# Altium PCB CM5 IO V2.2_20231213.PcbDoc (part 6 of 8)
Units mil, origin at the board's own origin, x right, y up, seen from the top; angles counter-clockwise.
Board outline 6299.61 x 3544.09 mil, 4 copper layers (Top, GND, Power, Bottom), stack 35.4 mil thick; 482 components, 404 nets, 1857 pads, 2731 vias.
Unrouted connection lines stored in the file: 1872.
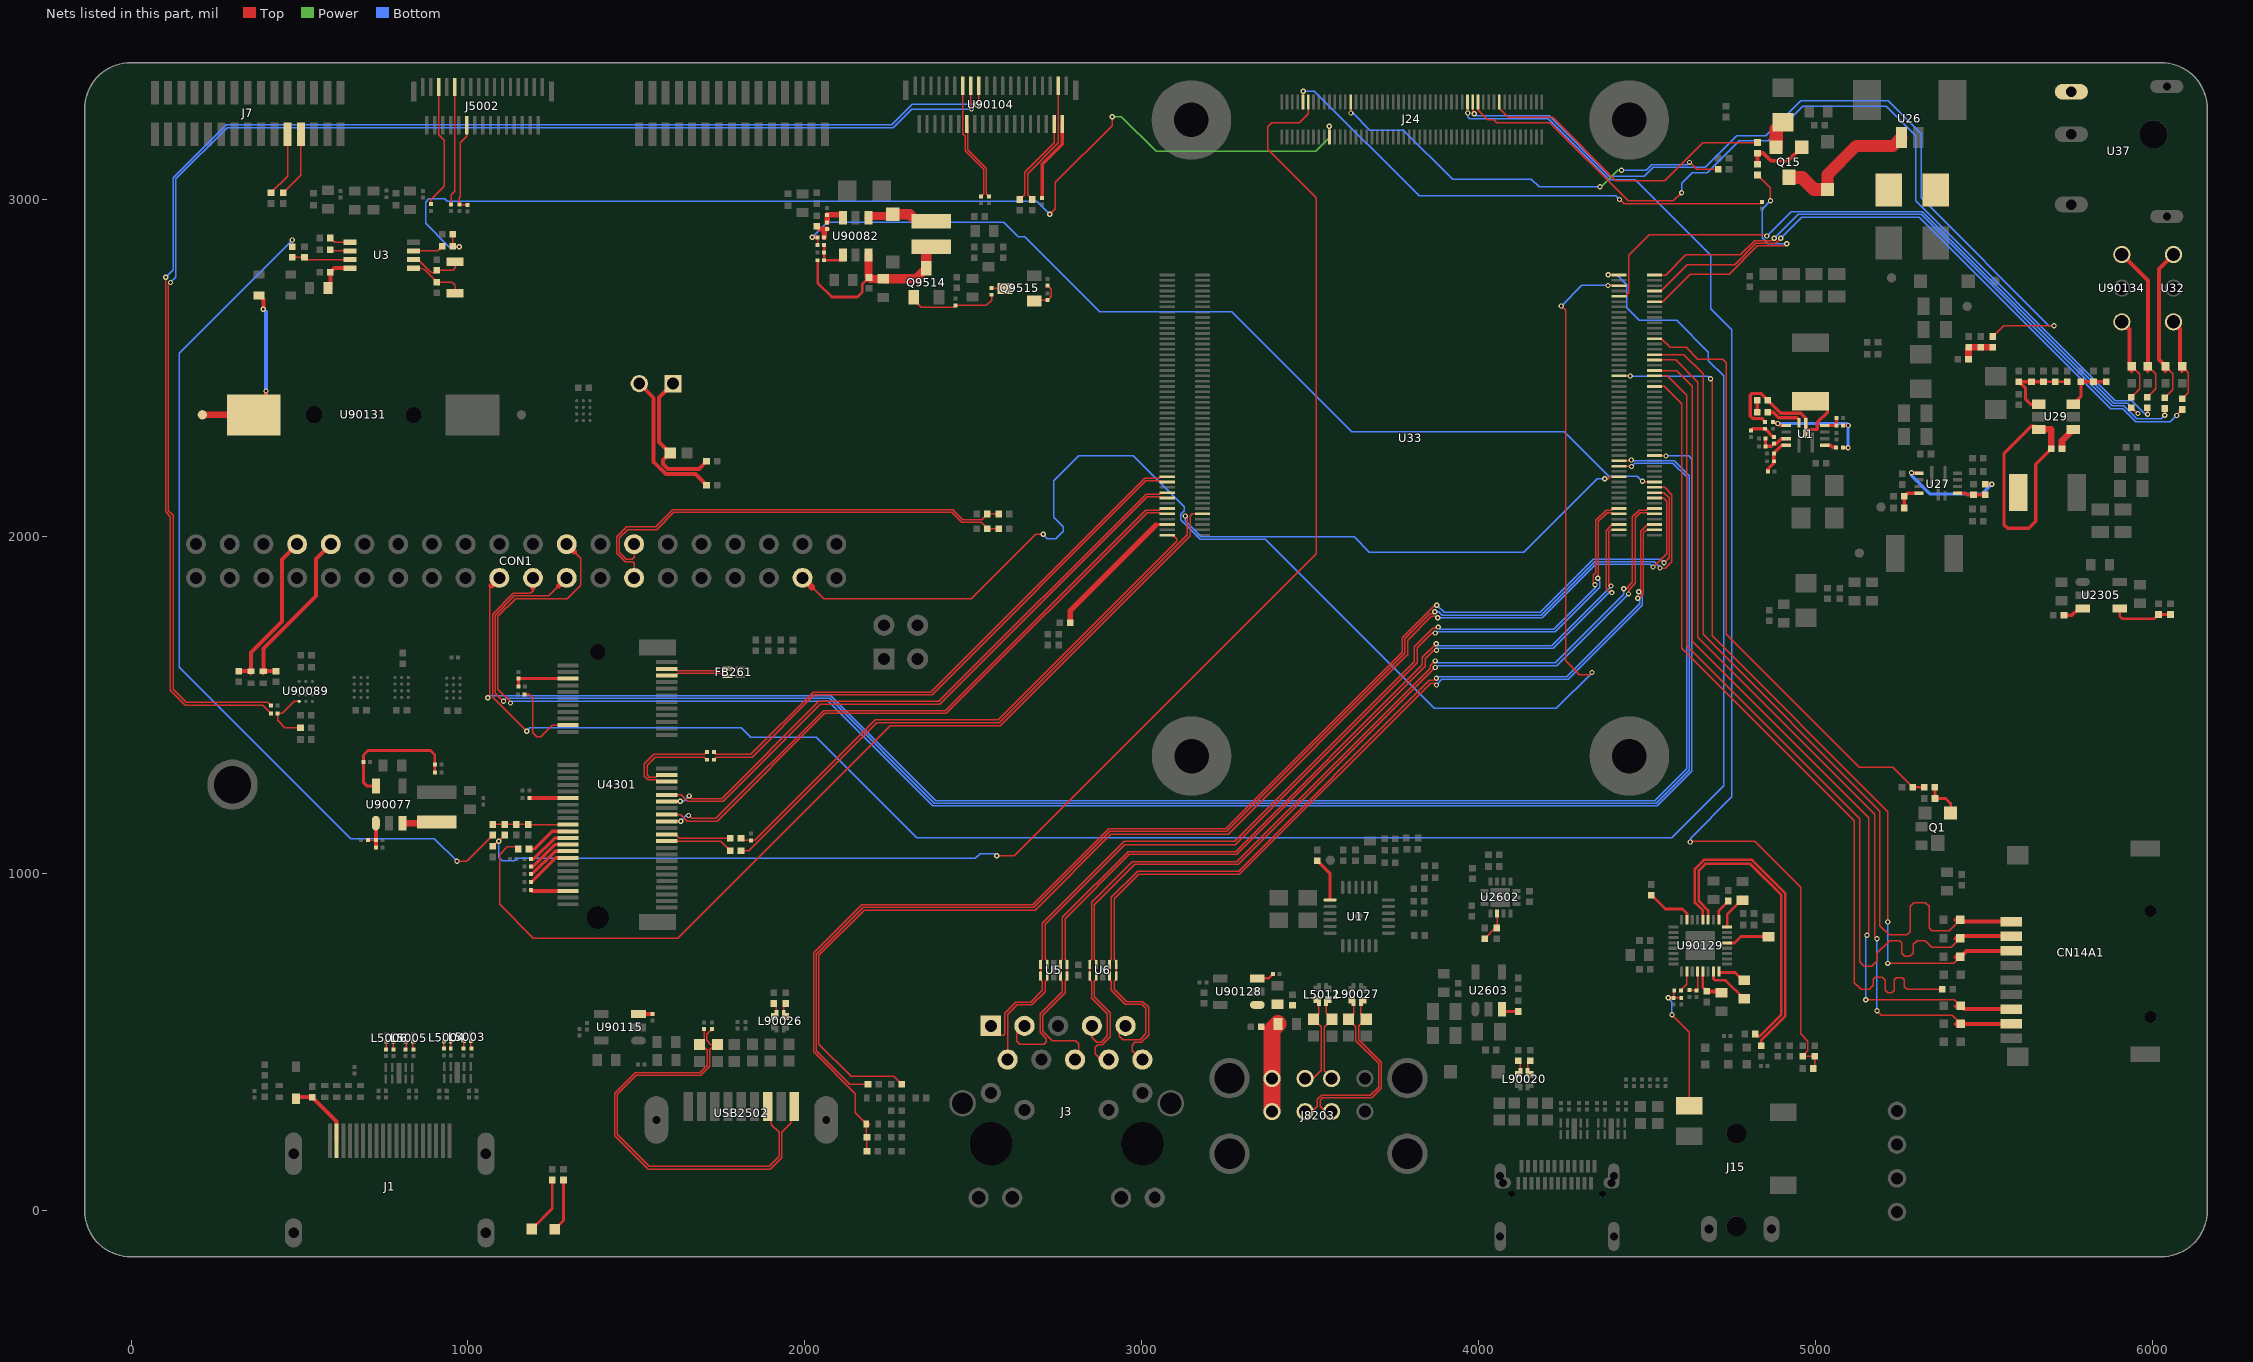
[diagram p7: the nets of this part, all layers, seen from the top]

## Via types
v1: diameter 15.75, hole 7.87, Top to Bottom, 2292 vias
v2: diameter 19.68, hole 11.81, Top to Bottom, 439 vias

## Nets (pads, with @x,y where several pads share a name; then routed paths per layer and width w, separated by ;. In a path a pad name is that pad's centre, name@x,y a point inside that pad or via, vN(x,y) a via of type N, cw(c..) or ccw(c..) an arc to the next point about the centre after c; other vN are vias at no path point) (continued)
N42932: C141.1 R151.1 R153.2 R154.2 | length 107.7
  Top w19.68: R151.1@5452.76,2524.61 5452.76,2560.04 C141.1@5453.74,2561.02 R154.2@5489.17,2561.02 R153.2@5524.61,2561.02
N43092: C143.1 R155.2 U27.6 | length 82.8
  Top w9.84: R155.2@5261.81,2083.66 C143.1@5261.81,2118.11
  Top w9.96: C143.1@5261.81,2118.11 5271.65,2127.95 U27.6@5306.1,2127.95
N43384: R156.1 U27.3 | length 322
  Top w9.84: v1(5283.46,2187.99) 5286.82,2187.01 U27.3@5306.1,2187.01 ; R156.1@5502.95,2154.53 v1(5521.65,2154.53)
  Bottom w9.84: v1(5283.46,2187.99) 5283.46,2181.06 5339.53,2125 5492.13,2125 v1(5521.65,2154.53)
N43388: C144.1 R156.2 U27.9 | length 84.7
  Top w9.84: U27.9@5420.28,2127.95 5443.9,2127.95 5448.82,2123.03 C144.1@5467.52,2123.03 R156.2@5502.95,2123.03
N43540: D45.1 D46.1 U37.1
N43676: C145.2 L13.1 U29.6 | length 788.7
  Top w9.84: U29.6@5661.42,2316.93 5651.57,2326.77 5639.57,2326.77 5558.07,2245.28 5558.07,2034.45 5568.9,2023.62 5631.89,2023.62 5652.56,2044.29 5652.56,2213.58 C145.2@5698.82,2259.84
  Top w19.68: U29.6@5661.42,2316.93 5698.82,2316.93 C145.2@5698.82,2259.84
N43804: C145.1 U29.1 | length 70.9
  Top w19.68: C145.1@5730.31,2259.84 5730.31,2283.46 U29.1@5763.78,2316.93
N46864: CON1.8 D49.2 R167.1 | length 470
  Top w11.81: R167.1@319.88,1599.41 D49.2@356.3,1599.41 356.3,1655.51 447.83,1747.05 447.83,1931.26 CON1.8@492.94,1976.36
N46956: CON1.10 D48.2 R168.1 | length 497.3
  Top w11.81: R168.1@430.12,1599.41 D48.2@392.72,1599.41 392.72,1666.34 549.21,1822.83 549.21,1932.63 CON1.10@592.94,1976.36
N87861: C1.1 D1.2 J1.18 | length 211.3
  Top w11.81: D1.2@490.16,330.71 490.16,335.63 C1.1@537.4,335.63 610.24,262.79 J1.18@610.24,206.69
N113472: C90425.1 L5003.4 R952.2 | length 23.5
  Top w3.94: L5003.4@1007.87,501.97 1007.87,481.3 C90425.1@1009.84,479.33
N113574: C90426.1 L5003.3 R953.2 | length 26.4
  Top w3.94: C90426.1@987.2,479.33 R953.2@987.2,502.95 988.98,502.95 L5003.3@988.98,501.97
N113748: C90427.1 L5004.4 R954.2 | length 24
  Top w3.94: L5004.4@947.83,500.98 R954.2@948.82,501.97 C90427.1@948.82,479.33
N113850: C90420.1 L5004.3 R955.2 | length 23.9
  Top w3.94: C90420.1@928.15,479.33 R955.2@928.15,501.97 928.94,501.18 L5004.3@928.94,500.98
N114042: C90421.1 L5005.4 R956.2 | length 23.5
  Top w3.94: L5005.4@835.63,500 835.63,479.33 C90421.1@837.6,477.36
N114144: C90422.1 L5005.3 R957.2 | length 23.4
  Top w3.94: C90422.1@814.96,477.36 816.73,479.13 L5005.3@816.73,500
N114322: C90424.1 L5006.4 R958.2 | length 23
  Top w3.94: L5006.4@777.56,500 777.56,478.35 C90424.1@778.54,477.36
N114424: C90423.1 L5006.3 R959.2 | length 24
  Top w3.94: C90423.1@756.89,477.36 757.87,478.35 R959.2@757.87,500.98
N131672: C90399.1 R95155.2 R95159.1 R95581.2 U4301.50 | length 222.9
  Top w3.94: R95155.2@1073.78,1144.67 R95581.2@1109.21,1144.67 R95159.1@1143.66,1144.67 C90399.1@1179.09,1144.67 1179.71,1144.05 U4301.50@1296.47,1144.05
N131914: R95147.2 U4301.54 | length 135.3
  Top w9.84: R95147.2@1186.97,1042.31 1195.85,1042.31 1258.23,1104.68 U4301.54@1296.47,1104.68
N131962: R95148.2 U4301.56 | length 137.8
  Top w9.84: R95148.2@1186.97,1019.67 1186.97,1018.82 1191.85,1018.82 1258.03,1085 U4301.56@1296.47,1085
N132002: R95149.2 U4301.58 | length 139
  Top w9.84: R95149.2@1186.97,997.03 1186.97,996.18 1189.1,996.18 1258.23,1065.31 U4301.58@1296.47,1065.31
N132062: R95150.2 U4301.60 | length 140.2
  Top w9.84: R95150.2@1186.97,974.4 1186.97,973.55 1187.82,973.55 1259.9,1045.63 U4301.60@1296.47,1045.63
N132134: R95152.2 U4301.70 | length 111
  Top w11.81: R95152.2@1186.97,950.77 1190.54,947.2 U4301.70@1296.47,947.2
N132294: L5011.1 U90077.3 | length 105.8
  Top w19.68: U90077.3@805.08,1148.61 L5011.1@907.48,1148.61
  Top w27.56: L5011.1@907.48,1148.61 L5011.1@907.48,1152
N132462: C269.1 R95209.2 R95239.2 U90077.1 | length 96.5
  Top w3.94: R95239.2@702.76,1098.43 C269.1@726.38,1098.43 C269.1@726.34,1098.46
  Top w11.81: C269.1@726.34,1098.46 U90077.1@726.34,1148.61 ; R95209.2@726.38,1075.79 C269.1@726.38,1098.43
N132478: C266.2 R95210.1 R95281.2 U90077.5 | length 398
  Top w7.87: R95210.1@689.92,1329.71 689.92,1350.35 703.74,1364.17 888.78,1364.17 901.57,1351.38 R95281.2@901.57,1321.85 C266.2@901.57,1298.23
  Top w9.84: R95210.1@689.92,1329.71 689.92,1268.7 699.78,1258.85 U90077.5@726.34,1258.85
N135689: FB261.3 R95141.1 U4301.3 | length 194.4
  Top w3.94: U4301.3@1589.78,1606.65 1616.14,1606.65 1621.42,1601.38 1752.95,1601.38 1758.86,1607.28 FB261.3@1764.76,1607.28 1764.76,1607.78 R95141.1@1779.04,1607.78
N135722: FB261.4 R95142.1 U4301.5 | length 195.7
  Top w3.94: U4301.5@1589.78,1586.97 1617.13,1586.97 1623.66,1593.5 1751.97,1593.5 1759.84,1585.63 FB261.4@1764.76,1585.63 1779.04,1585.63 R95142.1@1779.04,1585.14
N135883: C90392.2 U4301.35 | length 283.5
  Top w3.94: U4301.35@1589.78,1291.69 1563.35,1291.69 1557.09,1285.43 1538.39,1285.43 1531.5,1292.32 1531.5,1320.87 1555.12,1344.49 1701.77,1344.49 C90392.2@1709.65,1336.61
N135887: C90393.2 U4301.37 | length 310.1
  Top w3.94: U4301.37@1589.78,1272.01 1563.62,1272.01 1558.07,1277.56 1534.45,1277.56 1523.62,1288.39 1523.62,1324.8 1551.18,1352.36 1701.77,1352.36 C90393.2@1709.65,1360.24
N136147: R95144.2 U4301.53 | length 193.4
  Top w3.94: U4301.53@1589.78,1114.53 1616.14,1114.53 1627.32,1103.35 R95144.2@1778.54,1103.35
N136159: R95146.2 U4301.55 | length 200.3
  Top w3.94: U4301.55@1589.78,1094.84 1750.63,1094.84 R95146.2@1778.54,1066.93
N138588: R95143.2 U4301.42 | length 114.7
  Top w11.81: R95143.2@1182.05,1223.41 1182.49,1222.79 U4301.42@1296.47,1222.79
N139019: R95145.2 U4301.52 | length 137.2
  Top w9.84: R95145.2@1181.06,1071.84 1197.47,1071.84 1250,1124.37 U4301.52@1296.47,1124.37
N146153: R95467.2 U90104.2 | length 244.4
  Top w9.84: R95467.2@2703.74,3003.94 2703.74,3103.35 2763.78,3163.39 U90104.2@2763.78,3223.43
N146193: R95468.2 U90104.4 | length 266.8
  Top w3.94: R95468.2@2637.8,2999.02 2652.56,3013.78 2652.56,3079.72 2740.16,3167.32 U90104.4@2740.16,3223.43
N146409: R95469.2 U90104.23 | length 4397.4
  Top w3.94: v1(103.35,2768.7) 103.35,2071.85 117.13,2058.07 117.13,1542.32 160.43,1499.02 390.75,1499.02 R95469.2@415.35,1474.41 ; v1(2509.84,3280.51) 2515.75,3286.42 U90104.23@2515.75,3336.61
  Bottom w3.94: v1(103.35,2768.7) 125,2790.35 125,3063.3 282.17,3220.47 2257.87,3220.47 2318.9,3281.5 2505.91,3281.5 2508.37,3279.04 v1(2509.84,3280.51)
N146477: R95470.2 U90104.25 | length 4356.2
  Top w3.94: v1(117.13,2752.95) 111.22,2747.05 111.22,2075.79 125,2062.01 125,1546.26 164.37,1506.89 405.51,1506.89 R95470.2@415.35,1497.05 ; U90104.25@2492.13,3336.61 2492.13,3269.68 v1(2494.09,3267.72)
  Bottom w3.94: v1(117.13,2752.95) 132.87,2768.7 132.87,3060.04 285.43,3212.6 2261.81,3212.6 2316.93,3267.72 v1(2494.09,3267.72)
N146511: R95471.2 U90104.26 | length 242.9
  Top w3.94: U90104.26@2480.31,3223.43 2483.27,3220.48 2483.27,3146.65 2538.39,3091.54 2538.39,3015.75 R95471.2@2546.26,3007.87
N146519: R95472.2 U90104.27 | length 357.7
  Top w3.94: U90104.27@2468.5,3336.61 2468.5,3193.9 2475.39,3187.01 2475.39,3143.39 2530.51,3088.27 2530.51,3015.75 R95472.2@2522.63,3007.87
N16719677: C750.2 J5002.20 R715.2 | length 268.2
  Top w3.94: J5002.20@996.06,3219.5 996.06,3187.01 977.36,3168.31 977.36,3006.89 974.41,3003.94 C750.2@974.41,2984.25 997.05,2984.25 R715.2@998.03,2983.27
N16719795: J5002.23 R814.2 | length 352.9
  Top w3.94: R814.2@949.8,2984.25 949.8,3012.8 960.63,3023.62 J5002.23@960.63,3332.68
N16719909: J5002.27 R95580.2 | length 370.3
  Top w3.94: R95580.2@889.76,2985.24 889.76,2999.02 929.14,3038.39 929.14,3175.2 913.38,3190.95 J5002.27@913.38,3332.68
N16722445: C90408.1 C90410.1 L5000.1 Q9514.3 R95039.1 U90082.6 | length 606.3
  Top w7.87: R95039.1@2037.4,2818.9 2037.4,2751.97 2079.72,2709.65 2155.51,2709.65 2170.28,2724.41 2170.28,2748.03 C90410.1@2189.96,2767.72
  Top w23.62: U90082.6@2187.99,2834.65 2187.99,2769.68 C90410.1@2189.96,2767.72 2193.89,2763.78 C90408.1@2232.28,2763.78
  Top w27.56: C90408.1@2232.28,2763.78 2328.74,2763.78 Q9514.3@2360.24,2795.28
  Top w31.5: Q9514.3@2360.24,2795.28 2360.24,2859.25 L5000.1@2375,2859.25
N16722481: D5000.1 L5000.2 U90082.1 | length 206.8
  Top w23.62: U90082.1@2187.99,2944.88 2187.99,2950.3 2260.82,2950.3 D5000.1@2260.82,2955.71
  Top w31.5: D5000.1@2260.82,2955.71 2311.02,2955.71 2332.68,2934.06 L5000.2@2375,2934.06
N16722531: Q9514.1 R95041.2 R95044.1 | length 271.5
  Top w3.94: Q9514.1@2322.84,2708.66 2322.84,2701.77 2344.49,2680.12 2441.93,2680.12 R95041.2@2446.85,2685.04 2538.39,2685.04 2554.13,2700.79 R95044.1@2554.13,2716.54
N16722773: R95039.2 R95137.2 R95578.2 U90082.4 | length 117.1
  Top w7.87: R95137.2@2057.08,2864.17 R95578.2@2057.08,2841.54 R95039.2@2057.08,2818.9 2113.19,2818.9 U90082.4@2113.19,2834.65
N16722853: Q9515.3 R95044.2 | length 39.8
  Top w3.94: R95044.2@2554.13,2736.22 2592.52,2736.22 Q9515.3@2593.5,2735.24
N16722887: R95071.1 R95072.2 U90082.3 | length 78.7
  Top w15.75: R95072.2@2065.94,2931.1 R95071.1@2065.94,2953.74 2113.19,2953.74 U90082.3@2113.19,2944.88
N16723025: Q9515.1 R95042.2 R95043.1 | length 94
  Top w3.94: Q9515.1@2680.12,2697.84 2687.01,2697.84 2689.96,2700.79 R95043.1@2719.49,2700.79 2719.97,2700.79 2731.3,2712.12 2731.3,2732.28 R95042.2@2719.49,2744.09
N16723155: C90448.1 R95072.1 R95073.2 | length 58.4
  Top w15.75: C90448.1@2035.43,2919.29 2043.3,2911.42 2057.08,2911.42 ; R95073.2@2057.08,2886.81 2057.08,2911.42 ; R95072.1@2065.94,2911.42 2057.08,2911.42
N16734367: R95115.1 U1.8 | length 110.8
  Top w9.84: R95115.1@4857.28,2368.11 4873.03,2368.11 4889.76,2351.38 4943.89,2351.38 4949.8,2345.47 U1.8@4949.8,2336.61
N16734375: C90489.1 R95115.2 | length 35.4
  Top w9.84: R95115.2@4825.79,2368.11 C90489.1@4825.79,2403.54
N16734501: C90489.2 L5002.1 R95121.1 U1.7 | length 542.9
  Top w9.84: R95121.1@4849.41,2338.58 4849.41,2338.83 4838.83,2349.41 4812.28,2349.41 4805.12,2356.57 4805.12,2418.31 4810.04,2423.23 4838.51,2423.23 4857.74,2404 4857.28,2404 C90489.2@4857.28,2403.54 4895.67,2365.16 4954.72,2365.16 4969.49,2350.39 U1.7@4969.49,2320.86 4969.49,2304.85 4981.57,2316.93 5003.94,2316.93 5003.94,2337.6 5034.45,2368.11 5034.45,2400.59 L5002.1@4984.25,2400.59
N16734773: C90487.1 R95114.2 R95122.1 U1.12 | length 108.7
  Top w9.84: R95122.1@4857.28,2191.93 4857.28,2198.82 4875,2216.54 C90487.1@4875,2222.44 R95114.2@4875,2246.06 4898.62,2269.68 U1.12@4912.4,2269.68
N16734781: C90481.1 R95118.1 R95121.2 | length 82.3
  Top w9.84: C90481.1@4807.09,2313.98 4812.01,2318.9 R95121.2@4849.41,2318.9 4848.95,2318.9 4848.95,2318.44 4873.1,2294.29 R95118.1@4875.98,2294.29
N16735007: R95116.1 R95118.2 R95120.2 U1.11 | length 94
  Top w9.84: R95120.2@4850.39,2289.37 R95116.1@4850.39,2266.73 4868.11,2266.73 R95118.2@4875.98,2274.61 4882.35,2274.61 4897.11,2289.37 U1.11@4912.4,2289.37
N16735153: C90482.1 R95113.1 R95119.1 U1.9 | length 352.9
  Top w9.84: C90482.1@4873.03,2338.58 4873.03,2337.83 v1(4886.81,2334.65) 4892.71,2328.74 U1.9@4912.4,2328.74 ; R95113.1@5079.72,2262.8 v1(5095.47,2262.8) ; R95119.1@5080.71,2328.74 v1(5096.46,2328.74)
  Bottom w9.84: v1(4886.81,2334.65) 5090.55,2334.65 v1(5096.46,2328.74) 5095.47,2327.76 v1(5095.47,2262.8)
N16735287: R95113.2 U1.3 | length 36.9
  Top w9.84: U1.3@5026.58,2269.68 5043.31,2269.68 5049.21,2263.78 5060.04,2263.78 R95113.2@5060.04,2262.8
N16735291: R95117.1 R95119.2 U1.6 | length 57.1
  Top w9.84: U1.6@5026.58,2328.74 5035.44,2328.74 R95119.2@5061.02,2328.74 R95117.1@5061.02,2351.38
N16750686: L90020.1 R91188.2 R95546.1 | length 46.8
  Top w3.94: R95546.1@4151.57,403.54 4151.08,403.54 4151.08,403.05 4144.69,409.45 L90020.1@4144.69,412.4 4144.69,435.04 R91188.2@4152.56,442.91
N16750718: L90020.2 R91189.2 R95547.1 | length 44.9
  Top w3.94: R95547.1@4117.13,403.54 4117.37,403.54 4117.37,403.3 4123.03,408.96 L90020.2@4123.03,412.4 4123.03,437.01 R91189.2@4117.13,442.91
N16754417: R91193.1 U90115.3 | length 42.5
  Top w11.81: U90115.3@1505.91,581.69 1505.91,582.38 R91193.1@1547.7,582.38
N16755970: L90026.1 R95550.1 R95551.2 | length 43.9
  Top w3.94: R95550.1@1942.91,574.8 1942.67,574.8 1942.67,574.56 1937.01,580.22 L90026.1@1937.01,583.66 1937.01,607.28 R95551.2@1942.91,613.19
N16756054: L90026.2 R95552.2 R95553.1 | length 45.8
  Top w3.94: R95552.2@1907.48,613.19 1915.35,605.31 L90026.2@1915.35,583.66 1915.35,580.71 1908.96,574.31 1908.96,574.8 R95553.1@1908.46,574.8
N16763522: C90774.1 C90775.1 C90776.1 C90777.1 J8203.1 J8203.5 U90128.1 | length 267.8
  Top w51.18: J8203.1@3385.85,292.5 J8203.5@3385.85,390.93 3385.85,535.01 C90775.1@3403.77,552.93
N16763712: R95556.1 U90128.3 | length 51.6
  Top w7.87: U90128.3@3342.52,687.99 3375.98,687.99 R95556.1@3388.78,700.79
N16763936: ED21.1 J8203.2 L90027.3 R249.1 | length 565.4
  Top w3.94: J8203.2@3484.28,292.5 3504.12,292.5 3520.67,309.06 3520.67,328.89 3533.31,341.54 3678.15,341.54 3702.11,365.5 3702.11,435.38 3635.1,502.38 3635.1,544.03 ED21.1@3612.55,566.59 3628.29,582.34 L90027.3@3628.29,616.39 3628.29,618.85 3623.13,624.02 3623.13,623.28 R249.1@3622.39,623.28
N16763952: ED22.1 J8203.6 L5012.1 R253.2 | length 286.7
  Top w3.94: J8203.6@3484.28,390.93 3507.87,390.93 3531.72,414.77 3531.72,543.97 ED22.1@3509.16,566.52 3524.91,582.27 L5012.1@3524.91,616.33 3524.91,619.77 3519.25,625.43 3519.25,625.18 R253.2@3519,625.18
N16764114: ED20.1 J8203.3 L90027.4 R250.1 | length 570.4
  Top w3.94: J8203.3@3563.02,292.5 3544.29,292.5 3528.54,308.25 3528.54,325.63 3536.57,333.66 3681.41,333.66 3709.98,362.23 3709.98,438.64 3643.14,505.48 3643.14,547.24 3665.7,569.8 ED20.1@3665.7,566.59 3649.95,582.34 L90027.4@3649.95,616.39 3649.95,618.85 3655.11,624.02 3655.11,623.28 R250.1@3655.85,623.28
N16764134: ED6.1 J8203.7 L5012.2 R254.2 | length 263.7
  Top w3.94: R254.2@3552.47,625.18 3552.22,625.18 3552.22,625.43 3546.56,619.77 L5012.2@3546.56,616.33 3546.56,583.75 ED6.1@3563.98,566.34 3540.35,542.72 3540.35,413.59 J8203.7@3563.02,390.93
N16766215: R396.2 U90129.31 | length 146.4
  Top w7.87: R396.2@4511.81,935.04 4553.15,893.7 4603.53,893.7 4617.31,879.92 U90129.31@4617.31,861.84
N16766259: C560.1 U90129.28 | length 963.2
  Top w7.87: U90129.28@4664.55,861.84 4664.55,888.78 4640.75,912.59 4640.75,1012.8 4667.32,1039.37 4810.04,1039.37 4909.45,939.96 4909.45,575.79 4837.6,503.94 C560.1@4837.6,488.19
N16766319: C561.1 U90129.27 | length 910.1
  Top w7.87: U90129.27@4680.3,861.84 4680.3,889.81 4652.56,917.55 4652.56,1007.9 4672.22,1027.56 4805.12,1027.56 4897.64,935.04 4897.64,580.71 4833.66,516.73 4825.79,516.73 C561.1@4819.88,522.64
N16766443: C563.1 U90129.25 | length 67.2
  Top w7.87: U90129.25@4711.8,861.84 4711.8,888.96 C563.1@4740.16,917.32
N16766591: C564.1 U90129.24 | length 101.2
  Top w7.87: U90129.24@4736.4,840.18 4736.4,877.59 4778.73,919.91 C564.1@4782.66,919.91
N16766729: C565.1 U90129.21 | length 131.7
  Top w9.06: U90129.21@4736.4,792.94 4758.49,792.94 4777.56,812.01 4859.25,812.01 C565.1@4859.25,811.02
N16767009: R90340.1 U90129.10 | length 63.5
  Top w3.94: R90340.1@4599.32,652.28 4617.31,670.28 U90129.10@4617.31,708.29
N16767013: R95558.2 R95573.1 U90129.12 | length 78.5
  Top w3.94: R95558.2@4624.38,652.74 4645.67,652.74 R95573.1@4645.67,652.56 4648.81,655.7 U90129.12@4648.81,708.29
N16767017: C569.1 C570.1 U90129.13 | length 111.2
  Top w7.87: U90129.13@4664.55,708.29 4664.55,661.05 C570.1@4676.36,649.24
  Top w11.81: C570.1@4676.36,649.24 4719.67,649.24 C569.1@4719.67,645.3
N16767025: C568.1 U90129.15 | length 137.7
  Top w7.87: U90129.15@4696.05,708.29 4696.05,686.64 4700.6,682.09 4732.28,682.09 C568.1@4787.4,626.97
N16767069: C568.2 U90129.16 | length 88.2
  Top w7.87: U90129.16@4711.8,708.29 4711.8,705.34 4760.21,705.34 4783.46,682.09 C568.2@4787.4,682.09
N16767177: J15.4 R90337.2 R90340.2 R90341.1 | length 406.9
  Top w3.94: v1(4562.01,629.92) R90341.1@4577.76,629.92 ; v1(4572.83,579.72) 4624.04,528.52 J15.4@4624.04,310.22 ; R90340.2@4579.63,652.28 4577.76,650.41 R90341.1@4577.76,629.92 ; R90337.2@4600.39,629.92 R90341.1@4577.76,629.92
  Bottom w3.94: v1(4562.01,629.92) 4572.83,619.09 v1(4572.83,579.72)
N16770554: C90615.1 U3.1 Y2.2 | length 166.1
  Top w3.94: U3.1@838.57,2795.39 856.3,2795.39 cw(c856.3,2770.26) 874.06,2788.03 907.48,2754.61 C90615.1@907.48,2753.94 947.83,2753.94 cw(c947.83,2740.16) 961.61,2740.16 Y2.2@961.61,2721.46
N16770682: C90616.1 U3.2 Y2.1 | length 166.9
  Top w3.94: U3.2@838.57,2820.98 852.25,2820.98 886.86,2786.37 ccw(c898.62,2798.13) 898.62,2781.5 907.48,2781.5 C90616.1@907.48,2789.37 951.77,2789.37 ccw(c951.77,2799.21) 961.61,2799.21 Y2.1@961.61,2813.98
N16770702: C90617.1 R95373.2 U3.8 | length 117.1
  Top w11.81: R95373.2@584.65,2736.22 591.54,2736.22 C90617.1@591.54,2783.46 603.46,2795.39 U3.8@649.59,2795.39
N16770836: R95028.1 R95374.1 U3.7 | length 174.1
  Top w3.94: R95028.1@478.35,2827.76 R95374.1@514.76,2827.76 521.54,2820.98 U3.7@649.59,2820.98
N16770894: R121.2 U3.3 | length 90.3
  Top w3.94: U3.3@838.57,2846.57 909.56,2846.57 R121.2@923.23,2860.24
N16770902: R120.1 U3.6 | length 61.9
  Top w3.94: R120.1@591.54,2850.39 591.54,2846.57 U3.6@649.59,2846.57
N16771020: R95377.1 U3.5 | length 63.3
  Top w3.94: R95377.1@591.54,2884.84 604.22,2872.16 U3.5@649.59,2872.16
N16772975: D2.1 TP16.1 U90131.1 | length 552.2
  Top w11.81: U90131.1@364.25,2360.24 400.59,2360.24 v1(400.59,2431.1) ; D2.1@379.92,2714.92 392.72,2702.12 v1(392.72,2673.23)
  Top w19.68: TP16.1@211.61,2360.24 U90131.1@364.25,2360.24
  Bottom w11.81: v1(392.72,2673.23) 400.59,2665.35 v1(400.59,2431.1)
N16776017: ED4806.1 R95495.2 U32.1 | length 470.6
  Top w3.94: R95495.2@6035.43,2410.43 6059.06,2434.06 6059.06,2482.68 ED4806.1@6037.4,2504.33
  Top w11.81: ED4806.1@6037.4,2504.33 6017.72,2524.02 6017.72,2792.87 U32.1@6061.05,2836.2
N16801679: J7.4 R95570.2 | length 195.8
  Top w3.94: R95570.2@451.77,3018.7 503.94,3070.87 J7.4@503.94,3192.91
N16801700: J7.5 R95571.2 | length 194.6
  Top w3.94: R95571.2@415.35,3018.7 464.57,3067.91 J7.5@464.57,3192.91
N16808352: C153.1 R158.2 R159.2 R160.1 R95572.2 U29.4 | length 249.5
  Top w7.87: R95572.2@5675.2,2458.66 R158.2@5710.63,2458.66 R159.2@5746.06,2458.66
  Top w9.84: U29.4@5661.42,2391.73 5636.81,2391.73 5622.05,2406.5 5622.05,2438.98 C153.1@5602.36,2458.66 R160.1@5639.76,2458.66 R95572.2@5675.2,2458.66
N16810900: C148.2 R157.2 R161.1 U29.3 | length 151.1
  Top w9.84: U29.3@5763.78,2391.73 5786.42,2414.37 R161.1@5786.42,2458.66 C148.2@5823.82,2458.66 R157.2@5861.22,2458.66
N16815803: R2612.1 U2603.3 | length 52.1
  Top w7.87: U2603.3@4067.91,596.45 4074.8,589.57 R2612.1@4117.13,589.57
N16815967: R2613.2 R95599.2 U2602.5 | length 91.8
  Top w3.94: R2613.2@4017.35,805.87 4048.85,837.37 R95599.2@4052.78,837.37 4053.77,838.35 U2602.5@4053.77,880.28
N16884567: J24.92 R9241.2 | length 1535.3
  Top w3.94: J24.92@3477.76,3288.58 3478.35,3288.58 v1(3478.35,3320.87) ; v1(4417.32,2999.02) 4419.29,2999.02 4431.1,2987.2 4835.63,2987.2 R9241.2@4840.55,2992.13
  Bottom w3.94: v1(3478.35,3320.87) 3511.81,3320.87 3822.83,3009.84 4406.5,3009.84 v1(4417.32,2999.02)
N16901877: ED9203.1 R95582.2 U32.3 | length 254.8
  Top w3.94: R95582.2@6086.61,2407.48 6105.31,2426.18 6105.31,2485.63 ED9203.1@6086.61,2504.33
  Top w11.81: U32.3@6061.05,2636.2 6080.36,2616.89 6080.36,2510.93 6086.61,2504.68 ED9203.1@6086.61,2504.33
N16901998: R95583.2 R95598.1 U4301.6 | length 171.1
  Top w9.84: R95583.2@1149.61,1554.13 R95598.1@1149.61,1577.76 1296.47,1577.76 U4301.6@1296.47,1577.13
N16914632: ED9204.1 R95584.2 U90134.3 | length 255.8
  Top w3.94: R95584.2@5936.02,2412.4 5960.63,2437.01 5960.63,2480.71 ED9204.1@5937.01,2504.33
  Top w11.81: U90134.3@5907.9,2636.2 5930.76,2613.35 5930.76,2510.93 5937.01,2504.68 ED9204.1@5937.01,2504.33
N16914672: ED9205.1 R95585.2 U90134.1 | length 475.4
  Top w3.94: R95585.2@5983.27,2412.4 6007.87,2437.01 6007.87,2481.69 ED9205.1@5985.24,2504.33
  Top w11.81: U90134.1@5907.9,2836.2 5985.24,2758.87 ED9205.1@5985.24,2504.33
N16916775: R95586.2 U4301.20 | length 255.2
  Top w3.94: R95586.2@1168.27,1530.5 1181.1,1530.5 1191.93,1519.67 1191.93,1416.54 1203.94,1404.53 1215.55,1404.53 1250.35,1439.33 U4301.20@1296.47,1439.33
N16941764: LED4.2 R95602.1 | length 156.4
  Top w7.87: LED4.2@1257.62,-56.16 1283.46,-30.31 R95602.1@1283.46,89.57
N16946224: ED7104.1 J10.1 R7120.2 | length 421.9
  Top w11.81: J10.1@1608.27,2452.76 1566.93,2411.42 1566.93,2280.12 ED7104.1@1600,2247.05 1579.17,2226.22 1579.17,2214.13 1593.5,2199.8 1685.04,2199.8 R7120.2@1707.68,2222.44
N16946250: J10.2 R7125.1 | length 435.5
  Top w11.81: J10.2@1508.27,2452.76 1551.18,2409.84 1551.18,2219.85 1586.98,2184.06 1675.2,2184.06 R7125.1@1707.68,2151.57
N17002627: CON1.27 R95609.2 R95610.2 | length 1342.2
  Top w3.94: CON1.27@1492.94,1876.36 1492.94,1919.66 1488.39,1924.21 1466.73,1924.21 1441.34,1949.61 1441.34,1998.68 1471.01,2028.35 1556.91,2028.35 1607.3,2078.74 2438.58,2078.74 2468.11,2049.21 2524.61,2049.21 R95609.2@2541.34,2065.94 R95610.2@2574.8,2065.94
N17002814: CON1.28 R95611.1 R95612.1 | length 1312.6
  Top w3.94: CON1.28@1492.94,1976.36 1492.94,1937.82 1487.2,1932.09 1469.99,1932.09 1449.21,1952.87 1449.21,1995.42 1473.48,2019.68 1560.04,2019.68 1611.22,2070.87 2435.32,2070.87 2464.85,2041.34 2522.64,2041.34 R95612.1@2541.34,2022.64 R95611.1@2574.8,2022.64
N17057562: Q1.1 R12.2 R13.1 | length 114.7
  Top w7.87: R13.1@5352.85,1255.41 5353.35,1255.41 R12.2@5353.35,1221.46 5384.84,1221.46 5399.63,1206.67 Q1.1@5399.63,1178.86
N17076875: R2311.2 R95606.2 U2305.4 | length 181.8
  Top w7.87: U2305.4@5901.58,1785.43 5901.58,1762.8 5909.45,1754.92 6003.94,1754.92 R95606.2@6016.73,1767.72 R2311.2@6052.17,1767.72
N17076883: R2322.1 U2305.3 | length 63.3
  Top w9.84: R2322.1@5736.22,1765.75 5759.84,1765.75 5779.53,1785.43 U2305.3@5791.34,1785.43
N17101033: D37.1 Q15.3 U26.1 | length 439.7
  Top w35.43: D37.1@5034.45,3028.54 5034.45,3072.83 5120.08,3158.46 5229.33,3158.46 U26.1@5253.94,3183.07
  Top w39.37: Q15.3@4919.93,3065.25 4919.93,3064.32 4959.3,3064.32 4995.08,3028.54 D37.1@5034.45,3028.54
N17101108: Q15.1 R214.1 R215.1 | length 190.6
  Top w11.81: R214.1@4826.77,3103.35 R215.1@4826.77,3136.81 4843.5,3136.81 4866.14,3114.17 4917.8,3114.17 Q15.1@4957.93,3154.31
N17101132: Q15.2 R353.1 | length 82.6
  Top w39.37: Q15.2@4881.93,3154.31 4881.93,3207.72 R353.1@4902.56,3228.35
N17122158: R95616.1 U33.106 | length 429.9
  Top w7.87: 3041.34,2033.46 3042.92,2034.84 U33.106@3075.2,2034.84
  Top w15.75: R95616.1@2787.4,1743.11 2787.4,1779.53 3041.34,2033.46
N169418181: LED4.1 R95603.2 | length 170.8
  Top w7.87: LED4.1@1189.23,-56.05 1250,4.72 R95603.2@1250,89.57
OVCJ: R96.2 U17.1 | length 132.8
  Top w9.84: R96.2@3519.69,1037.4 3558.26,998.83 U17.1@3558.26,920.57
PCIE20_0_REFCLKN: U33.112 U4301.49 | length 1877.6
  Top w3.94: U4301.49@1589.78,1153.9 1589.78,1154.53 v1(1630.91,1154.53) ; v1(1654.53,1171.26) 1663.39,1162.4 1735.24,1162.4 2055.12,1482.28 2415.94,1482.28 3011.42,2077.76 3050.2,2077.76 3054.53,2082.09 U33.112@3075.2,2082.09
  Bottom w3.94: v1(1630.91,1154.53) 1647.64,1171.26 v1(1654.53,1171.26)
PCIE20_0_REFCLKP: U33.110 U4301.47 | length 1873.9
  Top w3.94: U4301.47@1589.78,1173.58 1631.89,1173.58 1650.94,1154.53 1739.17,1154.53 2059.06,1474.41 2419.88,1474.41 3015.35,2069.88 3051.18,2069.88 3054.72,2066.34 U33.110@3075.2,2066.34
PCIE20_0_RXN: U33.118 U4301.43 | length 1871.9
  Top w3.94: U4301.43@1589.78,1212.95 1589.78,1213.58 v1(1629.92,1213.58) ; v1(1656.5,1229.33) 1664.37,1221.46 1752.95,1221.46 2041.34,1509.84 2396.94,1509.84 3012.09,2125 3051.18,2125 3055.51,2129.33 U33.118@3075.2,2129.33
  Bottom w3.94: v1(1629.92,1213.58) 1640.75,1213.58 v1(1656.5,1229.33)
PCIE20_0_RXP: U33.116 U4301.41 | length 1869
  Top w3.94: U4301.41@1589.78,1232.64 1632.87,1232.64 1651.93,1213.58 1756.89,1213.58 2045.28,1501.97 2400.2,1501.97 3015.35,2117.13 3052.17,2117.13 3055.71,2113.58 U33.116@3075.2,2113.58
PCIE20_0_TXN: C90393.1 U33.124 | length 1690.5
  Top w3.94: C90393.1@1729.33,1360.24 1737.2,1352.36 1839.57,1352.36 2024.61,1537.4 2373.03,1537.4 3007.87,2172.24 3050.2,2172.24 3054.53,2176.57 U33.124@3075.2,2176.57
PCIE20_0_TXP: C90392.1 U33.122 | length 1690.2
  Top w3.94: C90392.1@1729.33,1336.61 1737.2,1344.49 1842.83,1344.49 2027.87,1529.53 2376.97,1529.53 3011.81,2164.37 3052.17,2164.37 3055.71,2160.83 U33.122@3075.2,2160.83
PCIE20X1_2_CLKREQN_M0: R95144.1 R95151.1 U33.102 | length 1703
  Top w3.94: R95144.1@1810.04,1103.35 1815.94,1097.44 R95151.1@1839.57,1097.44 1851.38,1097.44 2208.66,1454.72 2572.83,1454.72 3103.35,1985.24 3103.35,1991.81 3091.81,2003.35 U33.102@3075.2,2003.35
PCIE20X1_2_PERSTN_M0: R95145.1 U33.109 | length 2899.8
  Top w3.94: R95145.1@1149.57,1071.84 1142.66,1078.74 1117.13,1078.74 1093.5,1055.12 1093.5,907.48 1193.9,807.09 1622.05,807.09 2252.95,1437.99 2579.72,1437.99 3142.72,2000.98 3142.72,2060.04 3149.02,2066.34 U33.109@3179.13,2066.34
PCIE20X1_2_WAKEN_M0: R95146.1 U33.24 | length 3201.7
  Top w3.94: R95146.1@1810.04,1066.93 1832.68,1066.93 2212.6,1446.85 2576.1,1446.85 3133.86,2004.61 3133.86,2055.12 v1(3128.94,2060.04) ; v1(4373.03,2170.28) 4383.46,2170.28 4389.76,2176.57 U33.24@4415.75,2176.57
  Bottom w3.94: v1(3128.94,2060.04) 3128.94,2046.26 3176.59,1998.6 3629.35,1998.6 3675.2,1952.76 4132.87,1952.76 4350.39,2170.28 v1(4373.03,2170.28)
PHY1_LED0_Y1: R6.1 U33.19 | length 3813.5
  Top w3.94: R6.1@2187.01,374.02 2132.87,374.02 2033.46,473.43 2033.46,759.84 2172.24,898.62 2679.43,898.62 2904.83,1124.02 3252.14,1124.02 3780.2,1652.08 3780.2,1695.1 3854.78,1769.68 3863.19,1769.68 v1(3869.09,1775.59) ; U33.19@4520.47,2145.08 4550.79,2145.08 4572.44,2123.43 4572.44,2113.19 4572.44,1924.8 4553.15,1905.51 v1(4537.4,1905.51)
  Bottom w3.94: v1(3869.09,1775.59) 3880.91,1775.59 3890.75,1765.75 4184.73,1765.75 4343.2,1924.21 4520.47,1924.21 4538.39,1906.3 4538.39,1905.51 v1(4537.4,1905.51)
PHY1_LED1_G: D3.2 R2.2 R3.1 U33.17 | length 3959.1
  Top w3.94: R2.2@2184.06,175.2 R3.1@2184.06,216.54 2182.09,218.5 D3.2@2182.09,255.91 2149.61,288.39 2149.61,346.15 2025.59,470.16 2025.59,763.78 2168.31,906.5 2676.12,906.5 2901.52,1131.89 3248.87,1131.89 3772.32,1655.34 3772.32,1698.36 3869.23,1795.28 v1(3875,1795.28) ; U33.17@4520.47,2129.33 4548.82,2129.33 4564.57,2113.58 4564.57,1936.61 v1(4549.21,1921.26)
  Bottom w3.94: v1(3875,1795.28) 3896.65,1773.62 4181.47,1773.62 4339.93,1932.09 4537.4,1932.09 4548.72,1920.77 v1(4549.21,1921.26)
PHY1_LED2_Y: R5.1 U33.15 | length 3797.9
  Top w3.94: R5.1@2287.4,374.02 2263.78,397.64 2136.81,397.64 2041.34,493.11 2041.34,755.91 2176.18,890.75 2682.7,890.75 2908.1,1116.14 3255.4,1116.14 3784.79,1645.54 3788.07,1648.81 3788.07,1691.84 3858.04,1761.81 3874.02,1761.81 v1(3877.95,1757.87) ; v1(4516.73,1908.46) 4556.69,1948.43 4556.69,2103.35 4546.46,2113.58 U33.15@4520.47,2113.58
  Bottom w3.94: v1(3877.95,1757.87) 4187.99,1757.87 4346.46,1916.34 4508.86,1916.34 v1(4516.73,1908.46)
PHY1_MDI0+: J3.1 U5.1 U5.10 U33.12 | length 2837.5
  Top w3.94: J3.1@2551.39,547.01 2579.7,518.7 2589.57,518.7 2593.52,522.65 2593.52,584.65 2626,617.13 2669.29,617.13 2704.72,652.56 2704.72,679.13 2699.03,684.83 U5.1@2699.03,695.14 U5.10@2699.03,729.58 2699.03,739.17 2704.72,744.87 2704.72,852.15 2947.06,1094.49 3275.26,1094.49 3808.57,1627.8 3808.57,1671.68 3863.27,1726.38 3878.94,1726.38 v1(3878.94,1730.31) ; v1(4344.49,1856.3) 4341.54,1856.3 4338.58,1859.25 4338.58,1883.86 4346.46,1891.73 4346.46,2047.08 4377.14,2077.76 4392.72,2077.76 4397.05,2082.09 U33.12@4415.75,2082.09
  Bottom w3.94: v1(3878.94,1730.31) 3884.84,1724.41 4222.44,1724.41 4344.49,1846.46 v1(4344.49,1856.3)
PHY1_MDI0-: J3.2 U5.2 U5.9 U33.10 | length 2838.2
  Top w3.94: J3.2@2601.39,447.01 2601.39,580.71 2629.93,609.25 2673.23,609.25 2712.6,648.62 2712.6,678.15 2718.72,684.27 U5.2@2718.72,695.14 U5.9@2718.72,729.58 2718.72,740.16 2712.6,746.28 2712.6,848.43 2948.82,1084.65 3276.56,1084.65 3816.45,1624.54 3816.45,1668.4 3860.65,1712.6 v1(3870.08,1712.6) ; v1(4352.36,1875) 4354.33,1875 4354.33,2043.81 4380.4,2069.88 4392.72,2069.88 4396.26,2066.34 U33.10@4415.75,2066.34
  Bottom w3.94: v1(3870.08,1712.6) 3874.02,1716.54 4226.38,1716.54 4358.27,1848.43 4358.27,1866.14 4350.89,1873.52 v1(4352.36,1875)
PHY1_MDI1+: J3.3 U5.4 U5.7 U33.4 | length 2821.2
  Top w3.94: J3.3@2651.39,547.01 2633.86,547.01 2628.94,542.09 2628.94,501.97 2637.8,493.11 2709.65,493.11 2716.54,500 2716.54,508.86 2697.83,527.56 2697.83,582.68 2763.78,648.62 2763.78,678.15 2758.08,683.85 U5.4@2758.08,695.14 U5.7@2758.08,729.58 2758.08,739.17 2763.78,744.87 2763.78,868.89 2958.87,1063.98 3278.16,1063.98 3832.2,1618.01 3832.2,1640.27 v1(3873.03,1681.1) ; v1(4391.73,1852.36) 4389.76,1850.39 4385.83,1854.33 4385.83,2012.8 4392.13,2019.09 U33.4@4415.75,2019.09
  Bottom w3.94: v1(3873.03,1681.1) 3878.94,1675.2 4216.54,1675.2 4391.73,1850.39 v1(4391.73,1852.36)
PHY1_MDI1-: J3.6 U5.5 U5.6 U33.6 | length 2815.8
  Top w3.94: J3.6@2801.39,447.01 2812.99,458.61 2812.99,494.09 2804.13,502.95 2734.25,502.95 2705.71,531.5 2705.71,578.53 2771.65,644.48 2771.65,678.92 2777.77,685.04 U5.5@2777.77,695.14 U5.6@2777.77,729.58 2777.77,739.17 2771.65,745.29 2771.65,864.95 2962.81,1056.1 3281.42,1056.1 3840.07,1614.75 3840.07,1636.29 3865.2,1661.42 v1(3874.02,1661.42) ; v1(4393.7,1832.68) 4389.76,1832.68 4377.95,1844.49 4377.95,2009.84 4377.95,2016.73 4396.06,2034.84 U33.6@4415.75,2034.84
  Bottom w3.94: v1(3874.02,1661.42) 3879.92,1667.32 4220.47,1667.32 4387.8,1834.65 4391.73,1834.65 v1(4393.7,1832.68)
PHY1_MDI2+: J3.7 U6.1 U6.10 U33.11 | length 2803.8
  Top w3.94: J3.7@2851.39,547.01 2851.39,512.78 2865.16,499.02 2878.63,499.02 2897.64,518.03 2897.64,582.37 2850.39,629.61 2850.39,678.36 2844.7,684.06 U6.1@2844.7,695.14 U6.10@2844.7,729.58 2844.7,739.17 2850.39,744.87 2850.39,913.18 2971.67,1034.45 3282.04,1034.45 3855.82,1608.23 3855.82,1615.66 v1(3870.08,1629.92) ; v1(4430.12,1844.49) 4433.56,1841.04 4455.71,1863.19 4455.71,2058.07 4475.39,2077.76 4496.06,2077.76 4500.39,2082.09 U33.11@4520.47,2082.09
  Bottom w3.94: v1(3870.08,1629.92) 3875.98,1624.02 4226.38,1624.02 4430.12,1827.76 v1(4430.12,1844.49)
PHY1_MDI2-: J3.8 U6.2 U6.9 U33.9 | length 2806.4
  Top w3.94: J3.8@2901.39,447.01 2877.8,447.01 2861.22,463.58 2861.22,483.27 2869.09,491.14 2881.89,491.14 2905.51,514.76 2905.51,585.63 2858.27,632.87 2858.27,678.92 2864.39,685.04 U6.2@2864.39,695.14 U6.9@2864.39,729.58 2864.39,739.17 2858.27,745.29 2858.27,906.28 2978.56,1026.57 3285.3,1026.57 3868.96,1610.24 v1(3870.08,1610.24) ; v1(4443.9,1828.74) 4443.9,1840.24 4463.58,1859.93 4463.58,2054.13 4479.33,2069.88 4497.05,2069.88 4500.59,2066.34 U33.9@4520.47,2066.34
  Bottom w3.94: v1(3870.08,1610.24) 3875.98,1616.14 4231.3,1616.14 v1(4443.9,1828.74)
PHY1_MDI3+: J3.9 U6.4 U6.7 U33.3 | length 2804.1
  Top w3.94: J3.9@2951.39,547.01 2938.74,547.01 2933.07,541.34 2933.07,515.75 2942.91,505.91 2994.77,505.91 3011.81,522.95 3011.81,599.1 2999.69,611.22 2950.79,611.22 2909.45,652.56 2909.45,678.35 2903.75,684.06 U6.4@2903.75,695.14 U6.7@2903.75,729.58 2903.75,739.17 2909.45,744.87 2909.45,927.94 2987.41,1005.91 3286.91,1005.91 3853.21,1572.2 3867.55,1572.2 v1(3873.82,1578.47) ; v1(4471.46,1815.94) 4475.39,1815.94 4488.19,1828.74 4488.19,2009.84 4497.44,2019.09 U33.3@4520.47,2019.09
  Bottom w3.94: v1(3873.82,1578.47) 3878.03,1582.68 4260.83,1582.68 4477.36,1799.21 4477.36,1810.04 v1(4471.46,1815.94)
PHY1_MDI3-: J3.10 U6.5 U6.6 U33.5 | length 2809.8
  Top w3.94: J3.10@3001.39,447.01 2996.89,447.01 2970.47,473.43 2970.47,489.17 2979.33,498.03 2998.03,498.03 3019.69,519.68 3019.69,602.36 3002.95,619.09 2954.72,619.09 2918.31,655.51 2918.31,679.91 2923.44,685.04 U6.5@2923.44,695.14 U6.6@2923.44,729.58 2923.44,739.17 2917.32,745.29 2917.32,924 2990.37,997.05 3289.23,997.05 3856.45,1564.27 3868.11,1564.27 v1(3873.98,1558.41) ; v1(4474.41,1835.63) 4475.89,1834.15 4480.31,1838.58 4480.31,2014.02 4501.14,2034.84 U33.5@4520.47,2034.84
  Bottom w3.94: v1(3873.98,1558.41) 3890.37,1574.8 4264.76,1574.8 4485.24,1795.28 4485.24,1824.8 v1(4474.41,1835.63)
PWM4_M0: R214.2 U33.89 | length 756.8
  Top w3.94: U33.89@4520.47,2696.26 4545.67,2696.26 4626.97,2777.56 4742.13,2777.56 4825.79,2861.22 4906.5,2861.22 v1(4913.39,2868.11) ; R214.2@4826.77,3071.85 4865.16,3033.46 v1(4865.16,2995.08)
  Bottom w3.94: v1(4865.16,2995.08) 4840.55,2970.47 4840.55,2885.04 4857.48,2868.11 v1(4913.39,2868.11)
PWM11_M3: J24.18 R215.2 | length 921
  Top w3.94: J24.18@4060.43,3288.58 4060.43,3270.08 4065.94,3264.57 4065.94,3264.09 4086.92,3243.11 4218.5,3243.11 4406.5,3055.12 4551.18,3055.12 4664.37,3168.31 R215.2@4826.77,3168.31
PWM15_M1: R95073.1 R95137.1 U33.21 | length 2876.1
  Top w3.94: R95137.1@2037.4,2864.17 R95073.1@2037.4,2886.81 ; v1(4485.24,2163.39) 4485.24,2162.11 4520.47,2162.11 U33.21@4520.47,2160.83
  Top w9.84: v1(2021.65,2886.81) R95073.1@2037.4,2886.81
  Bottom w3.94: v1(2021.65,2886.81) 2065.94,2931.1 2590.24,2931.1 2632.76,2888.58 2652.76,2888.58 2875,2666.34 3266.17,2666.34 3622.47,2310.04 4252.95,2310.04 4384.84,2178.15 4470.47,2178.15 v1(4485.24,2163.39)
PWRON_L: R95495.1 U33.99 | length 1864.7
  Top w3.94: U33.99@4520.47,2775 4554.13,2775 4613.78,2834.65 4775.59,2834.65 4817.91,2876.97 4869.09,2876.97 v1(4875.98,2883.86) ; v1(6035.43,2359.25) R95495.1@6035.43,2378.94
  Bottom w3.94: v1(4875.98,2883.86) 4946.85,2954.72 5312.01,2954.72 5879.92,2386.81 5913.39,2386.81 5951.77,2348.43 6024.61,2348.43 v1(6035.43,2359.25)
RESET_L: R95584.1 U33.92 | length 1988.4
  Top w3.94: U33.92@4415.75,2712.01 4435.04,2712.01 4444.88,2721.85 4444.88,2833.66 4505.91,2894.68 4850.39,2894.68 v1(4854.33,2890.75) ; R95584.1@5936.02,2380.91 5952.76,2364.17 v1(5955.71,2364.17)
  Bottom w3.94: v1(4854.33,2890.75) 4854.33,2889.76 4927.17,2962.6 5315.94,2962.6 5883.86,2394.68 5925.2,2394.68 v1(5955.71,2364.17)
RSTB_CTP1: R95469.1 R95597.2 U90089.D1 | length 176.2
  Top w3.94: U90089.D1@499.02,1509.84 484.25,1509.84 448.82,1474.41 R95469.1@435.04,1474.41 435.04,1453.74 456.69,1432.09 R95597.2@502.95,1432.09
RTC_32K_IN: R95028.2 R95155.1 | length 2628.2
  Top w3.94: R95028.2@478.35,2859.25 v1(478.35,2878.94) ; v1(967.52,1035.43) 996.04,1035.43 R95155.1@1073.78,1113.18
  Bottom w3.94: v1(478.35,2878.94) 142.72,2543.31 142.72,1611.22 651.57,1102.36 900.59,1102.36 v1(967.52,1035.43)
RTC_32K_SOC: J24.90 R95581.1 R95614.1 | length 4406.3
  Top w3.94: R95614.1@1073.82,1079.72 1073.82,1082.09 v1(1091.54,1094.49) 1091.54,1095.5 R95581.1@1109.21,1113.18 ; v1(2568.9,1052.17) 2620.7,1052.17 3517.13,1948.59 3517.13,3004.19 3373.03,3148.28 3373.03,3214.88 3385.52,3227.36 3466.54,3227.36 3493.5,3254.33 J24.90@3493.5,3288.58
  Bottom w3.94: v1(1091.54,1094.49) 1091.54,1047.24 1101.38,1037.4 1137.8,1037.4 1144.69,1044.29 2505.91,1044.29 2519.69,1058.07 2562.99,1058.07 v1(2568.9,1052.17)
RTC_INT_L: J24.81 R121.1 R95375.2 | length 3260.2
  Top w3.94: R95375.2@954.72,2895.67 R121.1@954.72,2860.24 974.02,2860.24 v1(974.02,2858.66) ; v1(2726.38,2955.71) 2743.11,2972.44 2743.11,3050.2 2911.42,3218.5 v1(2911.42,3245.08) ; v1(3556.1,3216.54) 3556.1,3184.65 J24.81@3556.5,3184.65
  Power w3.94: v1(2911.42,3245.08) 2938.78,3245.08 3042.12,3141.73 3515.75,3141.73 3556.1,3182.09 v1(3556.1,3216.54)
  Bottom w3.94: v1(974.02,2858.66) 943.5,2858.66 874.02,2928.15 874.02,2991.14 883.86,3000.98 931.1,3000.98 937.99,2994.09 2687.99,2994.09 v1(2726.38,2955.71)
SARADC_VIN0_BOOT: R95582.1 U33.93 | length 1928.8
  Top w3.94: U33.93@4520.47,2727.76 4540.35,2727.76 4618.7,2806.1 4758.86,2806.1 4821.85,2869.09 4880.91,2869.09 v1(4895.67,2883.86) ; v1(6070.87,2358.27) 6078.74,2368.11 6078.74,2375.98 R95582.1@6086.61,2375.98
  Bottom w3.94: v1(4895.67,2883.86) 4958.66,2946.85 5307.09,2946.85 5875,2378.94 5910.12,2378.94 5949.49,2339.57 6052.17,2339.57 v1(6070.87,2358.27)
SARADC_VIN1_KEY/RECOVERY: J24.26 R95585.1 | length 2767.1
  Top w3.94: J24.26@3997.44,3288.58 3997.44,3264.17 4010.03,3251.59 4010.22,3251.59 4025.59,3236.22 4044.29,3236.22 4053.15,3227.36 4210.63,3227.36 4442.91,2995.08 4576.77,2995.08 v1(4601.38,3019.68) ; R95585.1@5983.27,2380.91 5984.25,2380.91 v1(5984.25,2362.2)
  Bottom w3.94: v1(4601.38,3019.68) 4601.38,3047.24 4632.87,3078.74 4677.78,3078.74 4772.27,3173.23 4857.9,3173.23 4961.25,3276.57 5208.04,3276.57 5296.26,3188.36 5296.26,2995.08 5888.78,2402.56 5937.01,2402.56 5977.36,2362.2 v1(5984.25,2362.2)
SARADC_VIN2_DC: J24.28 R153.1 | length 2512.8
  Top w3.94: J24.28@3981.69,3288.58 3981.69,3259.84 3987.6,3253.94 v1(3986.22,3253.94) ; R153.1@5524.61,2592.52 5557.09,2625 v1(5706.69,2625)
  Bottom w3.94: v1(3986.22,3253.94) 3993.11,3247.05 4208.29,3247.05 4387.43,3067.91 4490.16,3067.91 4516.73,3094.49 4671.26,3094.49 4765.75,3188.98 4851.38,3188.98 4954.72,3292.32 5214.57,3292.32 5312.01,3194.88 5312.01,3003.94 5690.94,2625 v1(5706.69,2625)
SARADC_VIN3_HP_HOOK: C7322.1 J24.30 R7314.1 R7315.2 | length 3730.8
  Top w3.94: J24.30@3965.94,3288.58 3966.54,3288.58 v1(3966.54,3255.91) ; v1(4626.97,1092.52) 4628.94,1094.49 4818.95,1094.49 4954.72,958.71 4954.72,523.62 4976.38,501.97 4976.38,472.44 R7315.2@4960.63,456.69 C7322.1@4996.06,456.69 4996.06,424.21 R7314.1@4992.13,420.28
  Bottom w3.94: v1(3966.54,3255.91) 3966.54,3245.08 3972.44,3239.17 4205.03,3239.17 4386.44,3057.76 4463.58,3057.76 4687.99,2833.35 4687.99,2675.2 4750.98,2612.2 4750.98,1226.13 4627.95,1103.1 4627.95,1092.52 v1(4626.97,1092.52)
SARADC_VIN4: CON1.37 U33.96 | length 4427
  Top w3.94: 2019.89,1849.41 2055.32,1813.98 2493.42,1813.98 2685.35,2005.91 v1(2706.69,2005.91) ; v1(4244.09,2683.07) 4257.28,2669.88 4257.28,1630.23 4297.95,1589.57 4329.72,1589.57 v1(4335.63,1595.47) ; v1(4382.87,2744.09) 4415.75,2744.09 U33.96@4415.75,2743.5
  Top w19.68: CON1.37@1992.94,1876.36 2019.89,1849.41
  Bottom w3.94: v1(2706.69,2005.91) 2719.49,1993.11 2744.88,1993.11 2766.73,2014.96 2766.73,2027.56 2738.19,2056.1 2738.19,2164.17 2812.21,2238.19 2974.41,2238.19 3125,2087.6 3125,2075.59 3115.16,2065.75 3115.16,2048.73 3173.16,1990.73 3365.57,1990.73 3867.13,1489.17 4229.33,1489.17 v1(4335.63,1595.47) ; v1(4244.09,2683.07) 4305.12,2744.09 v1(4382.87,2744.09)
SD_PWR_ON: R13.2 R95613.2 U33.75 | length 1824.1
  Top w3.94: U33.75@4520.47,2586.02 4541.34,2586.02 4567.32,2560.04 4615.3,2560.04 4649.75,2525.59 4723.23,2525.59 4734.25,2514.57 4734.25,1708.66 5128.94,1313.98 5228.35,1313.98 R95613.2@5286.91,1255.41
  Top w7.87: R95613.2@5286.91,1255.41 R13.2@5321.36,1255.41
SDMMC_CLK: R11.1 U33.57 | length 2425.7
  Top w3.94: U33.57@4520.47,2444.29 4550.2,2444.29 4601.38,2393.11 4601.38,1668.11 5114.17,1155.31 5114.17,675.2 5133.86,655.51 5158.46,655.51 5170.28,667.32 5170.28,685.04 5176.18,690.94 5196.85,690.94 5205.71,682.09 5205.71,652.56 5212.6,645.67 5225.39,645.67 5232.28,652.56 5232.28,684.06 5238.19,689.96 5256.89,689.96 5262.8,684.06 5262.8,663.39 5270.67,655.51 R11.1@5375,655.51
SDMMC_CMD: CN14A1.3 ED13.1 U33.62 | length 2609.4
  Top w3.94: U33.62@4415.75,2475.79 4448.43,2475.79 v1(4448.82,2475.39) ; v1(4687.01,2467.52) 4691.93,2462.6 4691.93,1704.42 5213.58,1182.76 v1(5213.58,855.31) ; v1(5213.58,732.28) 5408.86,732.28 ED13.1@5428.54,751.97
  Top w11.81: ED13.1@5428.54,751.97 5446.26,769.69 CN14A1.3@5579.5,769.69
  Bottom w3.94: v1(4448.82,2475.39) 4679.13,2475.39 v1(4687.01,2467.52) ; v1(5213.58,732.28) v1(5213.58,855.31)
SDMMC_D0: CN14A1.7 ED11.1 U33.63 | length 2618.9
  Top w3.94: U33.63@4520.47,2491.54 4586.61,2491.54 4632.87,2445.28 4632.87,1688.98 5157.48,1164.37 5157.48,821.85 v1(5151.57,815.94) ; v1(5147.64,624.02) 5147.64,625 5410.83,625 ED11.1@5429.53,606.3
  Top w11.81: ED11.1@5429.53,606.3 5439.37,596.46 CN14A1.7@5579.5,596.46
  Bottom w3.94: v1(5147.64,624.02) 5148.62,625 5148.62,812.99 v1(5151.57,815.94)
SDMMC_D1: CN14A1.8 ED10.1 U33.67 | length 2656.5
  Top w3.94: U33.67@4520.47,2523.03 4583.66,2523.03 4649.61,2457.09 4649.61,1699.8 5174.21,1175.2 5174.21,812.01 v1(5181.1,805.12) ; v1(5181.1,591.54) 5193.9,578.74 5403.94,578.74 ED10.1@5429.53,553.15
  Top w11.81: ED10.1@5429.53,553.15 CN14A1.8@5579.5,553.15
  Bottom w3.94: v1(5181.1,591.54) v1(5181.1,805.12)
SDMMC_D2: CN14A1.1 ED15.1 U33.69 | length 2598.4
  Top w3.94: U33.69@4520.47,2538.78 4608.27,2538.78 4665.35,2481.69 4665.35,1708.66 5189.96,1184.06 5189.96,844.49 5217.52,816.93 5269.69,816.93 5279.53,826.77 5279.53,901.57 5290.35,912.4 5324.8,912.4 5335.63,901.57 5335.63,837.6 5343.5,829.72 5396.06,829.72 ED15.1@5428.54,862.2
  Top w11.81: ED15.1@5428.54,862.2 5428.54,856.3 CN14A1.1@5579.5,856.3
SDMMC_D3: CN14A1.2 ED14.1 U33.61 | length 2608.7
  Top w3.94: U33.61@4520.47,2475.79 4559.06,2475.79 4617.13,2417.72 4617.13,1674.63 5129.92,1161.84 5129.92,737.2 5143.7,723.43 5165.35,723.43 5181.1,739.17 5181.1,762.8 5218.5,800.2 5248.03,800.2 5254.92,793.31 5254.92,761.81 5263.78,752.95 5278.54,752.95 5288.39,762.8 5288.39,788.39 5300.2,800.2 5323.82,800.2 5343.5,780.51 5401.97,780.51 ED14.1@5428.54,807.09
  Top w11.81: ED14.1@5428.54,807.09 5434.45,812.99 CN14A1.2@5579.5,812.99
SDMMC_DET_L: J24.74 R90334.1 | length 1254
  Top w3.94: J24.74@3619.49,3288.58 3620.08,3288.58 v1(3620.08,3255.91) ; v1(4625,3109.25) 4645.67,3088.58 R90334.1@4710.63,3088.58
  Power w3.94: v1(4359.25,3037.4) 4363.19,3037.4 4411.42,3085.63 v1(4423.23,3085.63)
  Bottom w3.94: v1(3620.08,3255.91) 3625,3255.91 3676.18,3204.72 3776.04,3204.72 3921.71,3059.06 4155.75,3059.06 4178.39,3036.42 4359.25,3036.42 v1(4359.25,3037.4) ; v1(4423.23,3085.63) 4496.06,3085.63 4512.8,3102.36 4618.11,3102.36 v1(4625,3109.25)
SENSOR_INT_LCD1: R95541.1 U90104.3 | length 381.2
  Top w3.94: R95541.1@2674.21,2999.02 2660.43,3012.8 2660.43,3075.79 2751.97,3167.32 U90104.3@2751.97,3336.61
SPIO_CLK_M1: CON1.23 U33.30 | length 5320.3
  Top w3.94: v1(1105.31,1509.84) 1080.71,1534.45 1080.71,1765.75 1137.8,1822.83 1239.41,1822.83 1268.94,1852.36 ; U33.30@4415.75,2223.82 4449.21,2223.82 v1(4451.77,2226.38)
  Top w15.75: 1268.94,1852.36 CON1.23@1292.94,1876.36
  Bottom w3.94: v1(1105.31,1509.84) 1104.33,1509.84 1113.19,1518.7 2072.83,1518.7 2383.86,1207.68 4525.59,1207.68 4624.02,1306.1 4624.02,2179.55 4579.16,2224.41 4453.74,2224.41 v1(4451.77,2226.38)
SPIO_CS0M1: CON1.24 U33.31 | length 5419.8
  Top w3.94: v1(1125.98,1504.92) 1127.85,1506.79 1088.58,1546.06 1088.58,1762.49 1141.06,1814.96 1294.29,1814.96 1334.25,1854.92 1334.25,1935.05 1315.76,1953.54 ; U33.31@4520.47,2239.57 4520.47,2238.19 v1(4555.12,2238.19)
  Top w15.75: CON1.24@1292.94,1976.36 1315.76,1953.54
  Bottom w3.94: v1(1125.98,1504.92) 1131.89,1510.83 2068.9,1510.83 2379.92,1199.8 4529.53,1199.8 4631.89,1302.17 4631.89,2228.35 4622.05,2238.19 v1(4555.12,2238.19)
SPIO_MISO_M1: CON1.21 U33.100 | length 6104.1
  Top w3.94: v1(1174.21,1421.26) 1072.83,1522.64 1072.83,1769.01 1134.53,1830.71 1185.43,1830.71 1192.94,1838.22 1192.94,1846.06 ; v1(4383.86,2775.59) 4415.75,2774.61 U33.100@4415.75,2775
  Top w15.75: 1192.94,1846.06 CON1.21@1192.94,1876.36
  Bottom w3.94: v1(1174.21,1421.26) 1174.21,1423.23 1183.07,1432.09 1811.02,1432.09 1839.57,1403.54 2033.46,1403.54 2331.69,1105.31 4572.83,1105.31 4726.38,1258.86 4726.38,2467.52 4726.38,2475.48 4681.1,2520.75 4681.1,2546.57 4586.92,2640.75 4476.38,2640.75 4438.98,2678.15 4438.98,2746.06 4409.45,2775.59 v1(4383.86,2775.59)
SPIO_MOSI_M1: CON1.19 U33.28 | length 5185.5
  Top w3.94: v1(1059.06,1520.67) 1064.96,1526.57 1064.96,1848.38 1069.33,1852.76 ; U33.28@4415.75,2208.07 4415.75,2207.61 4451.84,2207.61 v1(4452.76,2206.69)
  Top w15.75: 1069.33,1852.76 CON1.19@1092.94,1876.36
  Bottom w3.94: v1(1059.06,1520.67) 1064.96,1526.57 2076.77,1526.57 2387.8,1215.55 4521.65,1215.55 4616.14,1310.04 4616.14,2176.29 4575.9,2216.54 4462.6,2216.54 v1(4452.76,2206.69)
SSRX_1N: D90034.1 R91181.2 USB2502.5 | length 1282.1
  Top w3.94: R91181.2@1700.79,537.4 1700.79,505.31 D90034.1@1687.01,491.54 1687.01,494.29 1689.76,494.29 1709.56,474.49 1709.56,430.76 1687.26,408.46 1496.06,408.46 1435.04,347.44 1435.04,221.46 1534.45,122.05 1897.64,122.05 1931.1,155.51 1931.1,231.3 1957.68,257.87 1957.68,296.29 USB2502.5@1968.57,307.18
SSRX_1P: D90033.1 R91182.2 USB2502.6 | length 1276.1
  Top w3.94: R91182.2@1724.48,537.49 1708.66,521.68 1708.66,503.94 1721.06,491.54 D90033.1@1740.16,491.54 1733.27,491.54 1717.52,475.79 1717.52,427.58 1690.53,400.59 1499.32,400.59 1442.91,344.18 1442.91,224.72 1537.71,129.92 1893.7,129.92 1923.23,159.45 1923.23,231.3 1900.59,253.94 1900.59,296.42 USB2502.6@1889.83,307.18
